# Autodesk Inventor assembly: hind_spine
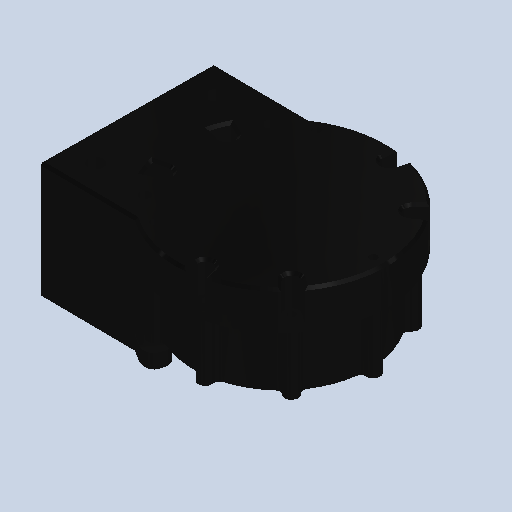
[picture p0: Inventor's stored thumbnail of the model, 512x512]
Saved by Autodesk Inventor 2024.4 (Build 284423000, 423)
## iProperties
Created: 2026-01
Part Number: hind_spine
Document SubType Name: Assembly
Designer: AdminForWorker
Title: hind_spine v1
Author: AdminForWorker
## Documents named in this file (4)
- c:\worker\convert-fusion-r06-cosv3\tmp\job-1\14\temp\files\7069be28-f26d-4d32-a85d-de0caccc6a05\hind_spine v1.iam
- c:\worker\convert-fusion-r06-cosv3\tmp\job-1\14\temp\files\7069be28-f26d-4d32-a85d-de0caccc6a05\CyberGear_1.ipt
- c:\worker\convert-fusion-r06-cosv3\tmp\job-1\14\temp\files\7069be28-f26d-4d32-a85d-de0caccc6a05\body_split1.ipt
- c:\worker\convert-fusion-r06-cosv3\tmp\job-1\14\temp\files\7069be28-f26d-4d32-a85d-de0caccc6a05\front_body.ipt
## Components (3 placed, 3 different names)
1. CyberGear:1
2. body_split1:1
3. front_body:1
